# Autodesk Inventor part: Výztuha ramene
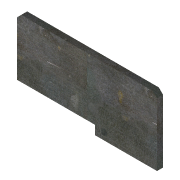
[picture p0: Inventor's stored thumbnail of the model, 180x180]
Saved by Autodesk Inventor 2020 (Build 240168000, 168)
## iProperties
Created: 2025-03
Part Number: Výztuha ramene
Material: Ocel
Document SubType Name: Modeling
Designer: doma
Density: 7.85 g/cm^3
Appearance: Plech
Mass: 1914.77 g
Surface Area: 559.475 cm^2
Volume: 243.92 cm^3
Author: doma
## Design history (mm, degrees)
sketch "Náčrt1"
  geometry: L1 (4837.128, 110.896)-(4940.128, 110.896); L2 (4940.128, 110.896)-(4940.128, 215.896); L3 (4940.128, 215.896)-(4933.128, 222.896); L4 (4933.128, 222.896)-(4714.128, 222.896); L5 (4714.128, 222.896)-(4707.128, 215.896); L6 (4707.128, 215.896)-(4707.128, 122.896); L7 (4837.128, 110.896)-(4837.128, 122.896); L8 (4837.128, 122.896)-(4707.128, 122.896); C1 r 5.5 at (4852.128, 122.896); 8 further points
  constraints: 16 end point, 1 centre point
extrude "Vysunutí1" new body sketch "Náčrt1" distance "d54" = 10; taper "d55" = 0 deg
chamfer "Zkosení1" distance "d56" = 3; stored, may be unused: second distance "d57" = 2, angle "d58" = 45 deg
chamfer "Zkosení2" distance "d59" = 5; stored, may be unused: second distance "d60" = 2, angle "d61" = 45 deg
node "Těleso1"
